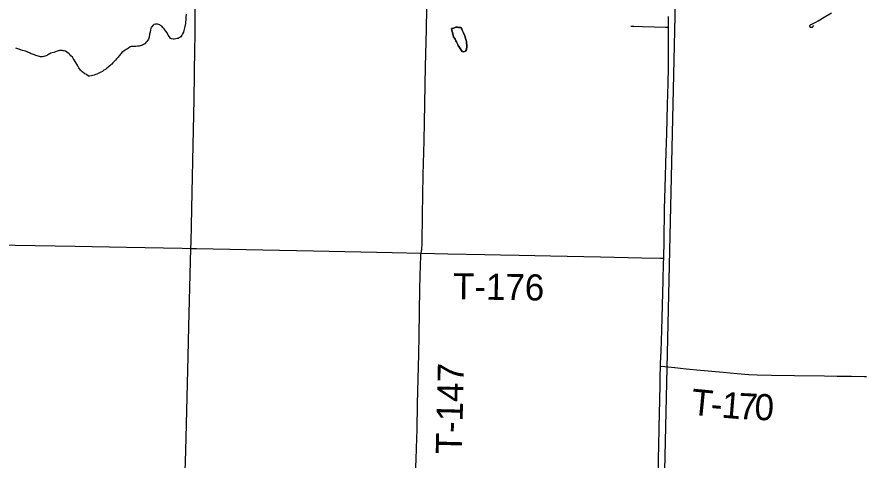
# Model space of a CAD drawing. Extents: x 2.1 to 73.9, y 4 to 26.
# Drawn here: x 45.891 to 46.811, y 19.072 to 19.554 of the extents above; entities that cross this region are included whole.
import ezdxf

# ---------------------------------------------------------------- set-up
doc = ezdxf.new("R2010")
doc.units = 0
for name, color, linetype in [('GM_X_County_Road', 7, 'Continuous'), ('GM_X_Minor_Lake', 7, 'Continuous'), ('GM_X_Minor_River', 7, 'Continuous'), ('GM_X_State_Route', 7, 'Continuous'), ('GM_X_Township_Road', 7, 'Continuous'), ('GM_X_Township_Road_Text', 7, 'Continuous')]:
    doc.layers.add(name, color=color, linetype=linetype)

msp = doc.modelspace()

# ---------------------------------------------------------------- linework, layer by layer
at = {"layer": 'GM_X_County_Road'}
for points in [[(46.33105, 19.29703), (46.33145, 19.29886), (46.33165, 19.29997), (46.33176, 19.30122), (46.33208, 19.30781), (46.33267, 19.33889), (46.33348, 19.38239), (46.33445, 19.41967), (46.33487, 19.43988), (46.33602, 19.50047), (46.33705, 19.54086), (46.33751, 19.56417)], [(45.57482, 19.31223), (45.57533, 19.31222), (45.62196, 19.31124), (45.6406, 19.31077), (45.65615, 19.31055), (45.73543, 19.30912), (45.80226, 19.30782), (45.82868, 19.30731), (45.84578, 19.30706), (45.87531, 19.30647), (45.88929, 19.30606), (45.95457, 19.30479), (46.01053, 19.30375), (46.07114, 19.30246), (46.08059, 19.30232)], [(46.08059, 19.30232), (46.08669, 19.30223), (46.17683, 19.30037), (46.19548, 19.30002), (46.21413, 19.29956), (46.29962, 19.29797), (46.33105, 19.29703)]]:
    msp.add_lwpolyline(points, dxfattribs=at)
at = {"layer": 'GM_X_Minor_Lake'}
for points in [[(46.38083, 19.52446), (46.38064, 19.5256), (46.38065, 19.52655), (46.38046, 19.52788), (46.38008, 19.52883), (46.37951, 19.53093), (46.37914, 19.53264), (46.37857, 19.53378), (46.37781, 19.53549), (46.37724, 19.53701), (46.37649, 19.53854), (46.37592, 19.54006), (46.37554, 19.5412), (46.37516, 19.54215), (46.37402, 19.54291), (46.37307, 19.54311), (46.37193, 19.54311), (46.3706, 19.5433), (46.36889, 19.54312), (46.36737, 19.54274), (46.36623, 19.54237), (46.36432, 19.5418), (46.36419, 19.54175)], [(46.36419, 19.54175), (46.36432, 19.5418), (46.36623, 19.54237), (46.36737, 19.54274), (46.36889, 19.54312), (46.3706, 19.5433), (46.37193, 19.54311), (46.37307, 19.54311), (46.37402, 19.54291), (46.37516, 19.54215), (46.37554, 19.5412), (46.37592, 19.54006), (46.37649, 19.53854), (46.37724, 19.53701), (46.37781, 19.53549), (46.37857, 19.53378), (46.37914, 19.53264), (46.37951, 19.53093), (46.38008, 19.52883), (46.38046, 19.52788), (46.38065, 19.52655), (46.38064, 19.5256), (46.38083, 19.52446), (46.38083, 19.52351), (46.38083, 19.52237), (46.38102, 19.52123), (46.38063, 19.52009), (46.38044, 19.51895), (46.3793, 19.51724), (46.37834, 19.51668), (46.37701, 19.5163), (46.37587, 19.51668), (46.37492, 19.51802), (46.3736, 19.51992), (46.37284, 19.52106), (46.37208, 19.52221), (46.37151, 19.52316), (46.37094, 19.52449), (46.37019, 19.52601), (46.36962, 19.52715), (46.36905, 19.52849), (46.36829, 19.5302), (46.36735, 19.53115), (46.3664, 19.53286), (46.36583, 19.5342), (46.36419, 19.54175)], [(46.36419, 19.54175), (46.36583, 19.5342), (46.3664, 19.53286), (46.36735, 19.53115), (46.36829, 19.5302), (46.36905, 19.52849), (46.36962, 19.52715), (46.37019, 19.52601), (46.37094, 19.52449), (46.37151, 19.52316), (46.37208, 19.52221), (46.37284, 19.52106), (46.3736, 19.51992), (46.37492, 19.51802), (46.37587, 19.51668), (46.37701, 19.5163), (46.37834, 19.51668), (46.3793, 19.51724), (46.38044, 19.51895), (46.38063, 19.52009), (46.38102, 19.52123), (46.38083, 19.52237), (46.38083, 19.52351), (46.38083, 19.52446)]]:
    msp.add_lwpolyline(points, dxfattribs=at)
at = {"layer": 'GM_X_Minor_River'}
for points in [[(46.60821, 19.6038), (46.59551, 19.04415), (46.60176, 19.0314), (46.61094, 18.95554), (46.6172, 18.94925), (46.66663, 18.73187), (46.7097, 18.68232), (46.805, 18.10511)], [(46.07534, 19.55727), (46.07515, 19.55404), (46.07495, 19.55157), (46.07476, 19.54853), (46.07456, 19.54739), (46.07399, 19.54416), (46.07322, 19.54112), (46.07284, 19.5398), (46.07245, 19.5379), (46.0715, 19.53619), (46.07073, 19.53448), (46.0694, 19.53277), (46.06845, 19.53221), (46.0675, 19.53164), (46.06654, 19.53107), (46.06559, 19.53088), (46.06426, 19.53051), (46.06236, 19.53013), (46.06103, 19.53014), (46.05932, 19.53052), (46.05837, 19.5311), (46.05723, 19.53262), (46.05571, 19.53471), (46.05458, 19.537), (46.05325, 19.5389), (46.05211, 19.54043), (46.05135, 19.54138), (46.05022, 19.54271), (46.04889, 19.54423), (46.04756, 19.545), (46.04661, 19.54576), (46.04547, 19.54634), (46.04433, 19.54653), (46.04338, 19.54672), (46.04186, 19.54654), (46.04034, 19.54616), (46.03919, 19.54521), (46.03805, 19.5437), (46.0371, 19.54332), (46.03671, 19.54047), (46.03614, 19.53781), (46.03556, 19.53572), (46.03537, 19.53439), (46.03518, 19.53344), (46.03498, 19.5323), (46.0346, 19.53116), (46.03422, 19.53021), (46.03346, 19.52908), (46.03269, 19.52756), (46.03155, 19.52661), (46.03021, 19.52509), (46.02907, 19.52434), (46.02774, 19.52358), (46.0266, 19.5232), (46.02546, 19.52283), (46.02412, 19.52245), (46.02222, 19.52246), (46.02051, 19.52227), (46.01899, 19.52228), (46.01804, 19.52228), (46.01671, 19.52228), (46.01557, 19.52229), (46.01424, 19.52172), (46.01252, 19.52058), (46.01157, 19.51983), (46.01005, 19.51888), (46.00891, 19.51812), (46.00776, 19.51737), (46.00548, 19.51566), (46.00471, 19.51472), (46.00395, 19.51377), (46.003, 19.51282), (46.00224, 19.51187), (46.00128, 19.51054), (45.99938, 19.50884), (45.99843, 19.50751), (45.99747, 19.50637), (45.99652, 19.50562), (45.99557, 19.50429), (45.99442, 19.50315), (45.99328, 19.50221), (45.99214, 19.50107), (45.99099, 19.50012), (45.98966, 19.49918), (45.98852, 19.49842), (45.98757, 19.49728), (45.98566, 19.49634), (45.98414, 19.4952), (45.98262, 19.49426), (45.9809, 19.4935), (45.97957, 19.49274), (45.97824, 19.49218), (45.97672, 19.4918), (45.97519, 19.49105)], [(45.97519, 19.49105), (45.97367, 19.49067), (45.97234, 19.49048), (45.97006, 19.49011), (45.96911, 19.49011), (45.96683, 19.49164), (45.96493, 19.4926), (45.96322, 19.49393), (45.96208, 19.4947), (45.96113, 19.49565), (45.96018, 19.4966), (45.95848, 19.49908), (45.95734, 19.50117), (45.95355, 19.50764), (45.95242, 19.50916), (45.95147, 19.5105), (45.94995, 19.51221), (45.94881, 19.51336), (45.94786, 19.51431), (45.94691, 19.51507), (45.94558, 19.51603), (45.94406, 19.51698), (45.94254, 19.51736), (45.94159, 19.51756), (45.94064, 19.51775), (45.93969, 19.51775), (45.93855, 19.51776), (45.9376, 19.51776), (45.93627, 19.51738), (45.93494, 19.51701), (45.93304, 19.51644), (45.93113, 19.51588), (45.92961, 19.5155), (45.92809, 19.51494), (45.92638, 19.51399), (45.92542, 19.51342), (45.92428, 19.51286), (45.92295, 19.5121), (45.92162, 19.51172), (45.92048, 19.51135), (45.91914, 19.51116), (45.918, 19.51116), (45.91667, 19.51117), (45.91572, 19.51136), (45.91439, 19.51155), (45.91306, 19.51213), (45.91154, 19.51251), (45.91021, 19.51309), (45.90907, 19.51366), (45.90793, 19.51404), (45.9066, 19.51443), (45.90565, 19.51481), (45.9047, 19.51538), (45.90356, 19.51577), (45.90147, 19.51672), (45.90033, 19.51711), (45.899, 19.51749), (45.89729, 19.51806), (45.89216, 19.51979), (45.89007, 19.52037)]]:
    msp.add_lwpolyline(points, dxfattribs=at)
at = {"layer": 'GM_X_State_Route'}
for points in [[(46.08059, 19.30232), (46.08077, 19.30902), (46.08199, 19.3634), (46.08282, 19.41468), (46.08392, 19.4644), (46.08493, 19.52035), (46.08508, 19.53278), (46.0852, 19.55453), (46.08591, 19.59183), (46.08625, 19.60736), (46.08649, 19.61823), (46.08701, 19.63688), (46.08758, 19.65551), (46.08792, 19.66482), (46.08846, 19.68812), (46.08915, 19.72231), (46.08999, 19.77515), (46.09063, 19.80873)], [(46.07151, 18.93015), (46.07174, 18.93922), (46.07245, 18.97495), (46.07284, 18.99827), (46.074, 19.04954), (46.07405, 19.05121), (46.07452, 19.06974), (46.07524, 19.09615), (46.07673, 19.1552), (46.07739, 19.18472), (46.07824, 19.21735), (46.08059, 19.30232)]]:
    msp.add_lwpolyline(points, dxfattribs=at)
at = {"layer": 'GM_X_Township_Road'}
for points in [[(46.60047, 19.5434), (46.60052, 19.5502), (46.60053, 19.55484)], [(46.75763, 19.54512), (46.7577, 19.54481), (46.75766, 19.54412), (46.75741, 19.5436), (46.75716, 19.54332), (46.75685, 19.54309), (46.75628, 19.54285), (46.75595, 19.54284), (46.75541, 19.54294), (46.75506, 19.5431), (46.75478, 19.54326), (46.75457, 19.5435), (46.75438, 19.54404), (46.7543, 19.54461), (46.75437, 19.54499), (46.75453, 19.54533), (46.75496, 19.54579), (46.75527, 19.54603), (46.7557, 19.54626), (46.75632, 19.54658), (46.75796, 19.54736), (46.75919, 19.548), (46.76067, 19.54871), (46.76321, 19.55016), (46.76972, 19.55405), (46.77765, 19.55888)], [(46.55944, 19.54432), (46.5626, 19.5443), (46.57205, 19.54406), (46.58466, 19.54366), (46.59726, 19.54345), (46.60047, 19.5434)], [(46.59519, 19.29185), (46.59558, 19.31107), (46.59617, 19.34524), (46.59678, 19.36853), (46.59799, 19.40735), (46.59862, 19.42754), (46.59942, 19.45859), (46.60016, 19.48188), (46.60039, 19.49896), (46.60038, 19.51294), (46.60044, 19.53934), (46.60047, 19.5434)], [(45.57482, 19.31223), (45.57533, 19.31222), (45.62196, 19.31124), (45.6406, 19.31077), (45.65615, 19.31055), (45.73543, 19.30912), (45.80226, 19.30782), (45.82868, 19.30731), (45.84578, 19.30706), (45.87531, 19.30647), (45.88929, 19.30606), (45.95457, 19.30479), (46.01053, 19.30375), (46.07114, 19.30246), (46.08059, 19.30232)], [(46.08059, 19.30232), (46.08669, 19.30223), (46.17683, 19.30037), (46.19548, 19.30002), (46.21413, 19.29956), (46.29962, 19.29797), (46.33105, 19.29703)], [(46.32489, 19.04582), (46.32507, 19.05098), (46.32518, 19.05408), (46.32516, 19.05872), (46.3253, 19.0649), (46.32558, 19.07263), (46.32594, 19.08502), (46.32663, 19.10516), (46.32733, 19.13305), (46.32862, 19.18728), (46.32893, 19.20742), (46.32985, 19.25856), (46.33046, 19.2849), (46.33067, 19.29373), (46.33075, 19.29523), (46.33105, 19.29703)], [(46.33105, 19.29703), (46.36016, 19.29641), (46.40054, 19.29575), (46.41762, 19.29536), (46.43781, 19.29494), (46.47197, 19.29422), (46.52632, 19.2932), (46.57136, 19.29229), (46.59155, 19.29191), (46.59519, 19.29185)], [(46.59173, 19.17427), (46.59182, 19.17754), (46.59224, 19.18996), (46.59303, 19.21324), (46.59451, 19.26759), (46.59507, 19.28622), (46.59519, 19.29185)], [(46.5916, 19.04336), (46.59133, 19.04417), (46.59064, 19.04719), (46.59007, 19.05181), (46.58958, 19.05955), (46.58938, 19.0673), (46.58945, 19.07506), (46.58975, 19.08592), (46.59022, 19.10766), (46.59085, 19.13716), (46.59128, 19.15425), (46.59142, 19.16201), (46.59173, 19.17427)], [(46.59173, 19.17427), (46.59638, 19.17377), (46.6072, 19.17261), (46.61958, 19.17138), (46.63505, 19.16983), (46.65982, 19.16744), (46.67531, 19.166), (46.68771, 19.16503), (46.69703, 19.16458), (46.71258, 19.16423), (46.73747, 19.16408), (46.77012, 19.16358), (46.78412, 19.16343), (46.79967, 19.16322), (46.81365, 19.16288), (46.81593, 19.16278)]]:
    msp.add_lwpolyline(points, dxfattribs=at)

# ---------------------------------------------------------------- texts
at = {"layer": 'GM_X_Township_Road_Text'}
for s, height, rotation, p in [('T-176', 0.028409, 359.16466, (46.36569, 19.24703)), ('T-147', 0.028409, 88.59454, (46.37537, 19.07799)), ('T', 0.02841, 354.35956, (46.62412, 19.12143)), ('1', 0.02841, 355.23351, (46.65736, 19.1182)), ('7', 0.02841, 356.99971, (46.67575, 19.11668)), ('0', 0.02841, 357.6046, (46.69355, 19.11575)), ('-', 0.02841, 354.56956, (46.64538, 19.11933))]:
    msp.add_text(s, height=height, rotation=rotation, dxfattribs=at).set_placement(p)

doc.saveas('drawing.dxf')
